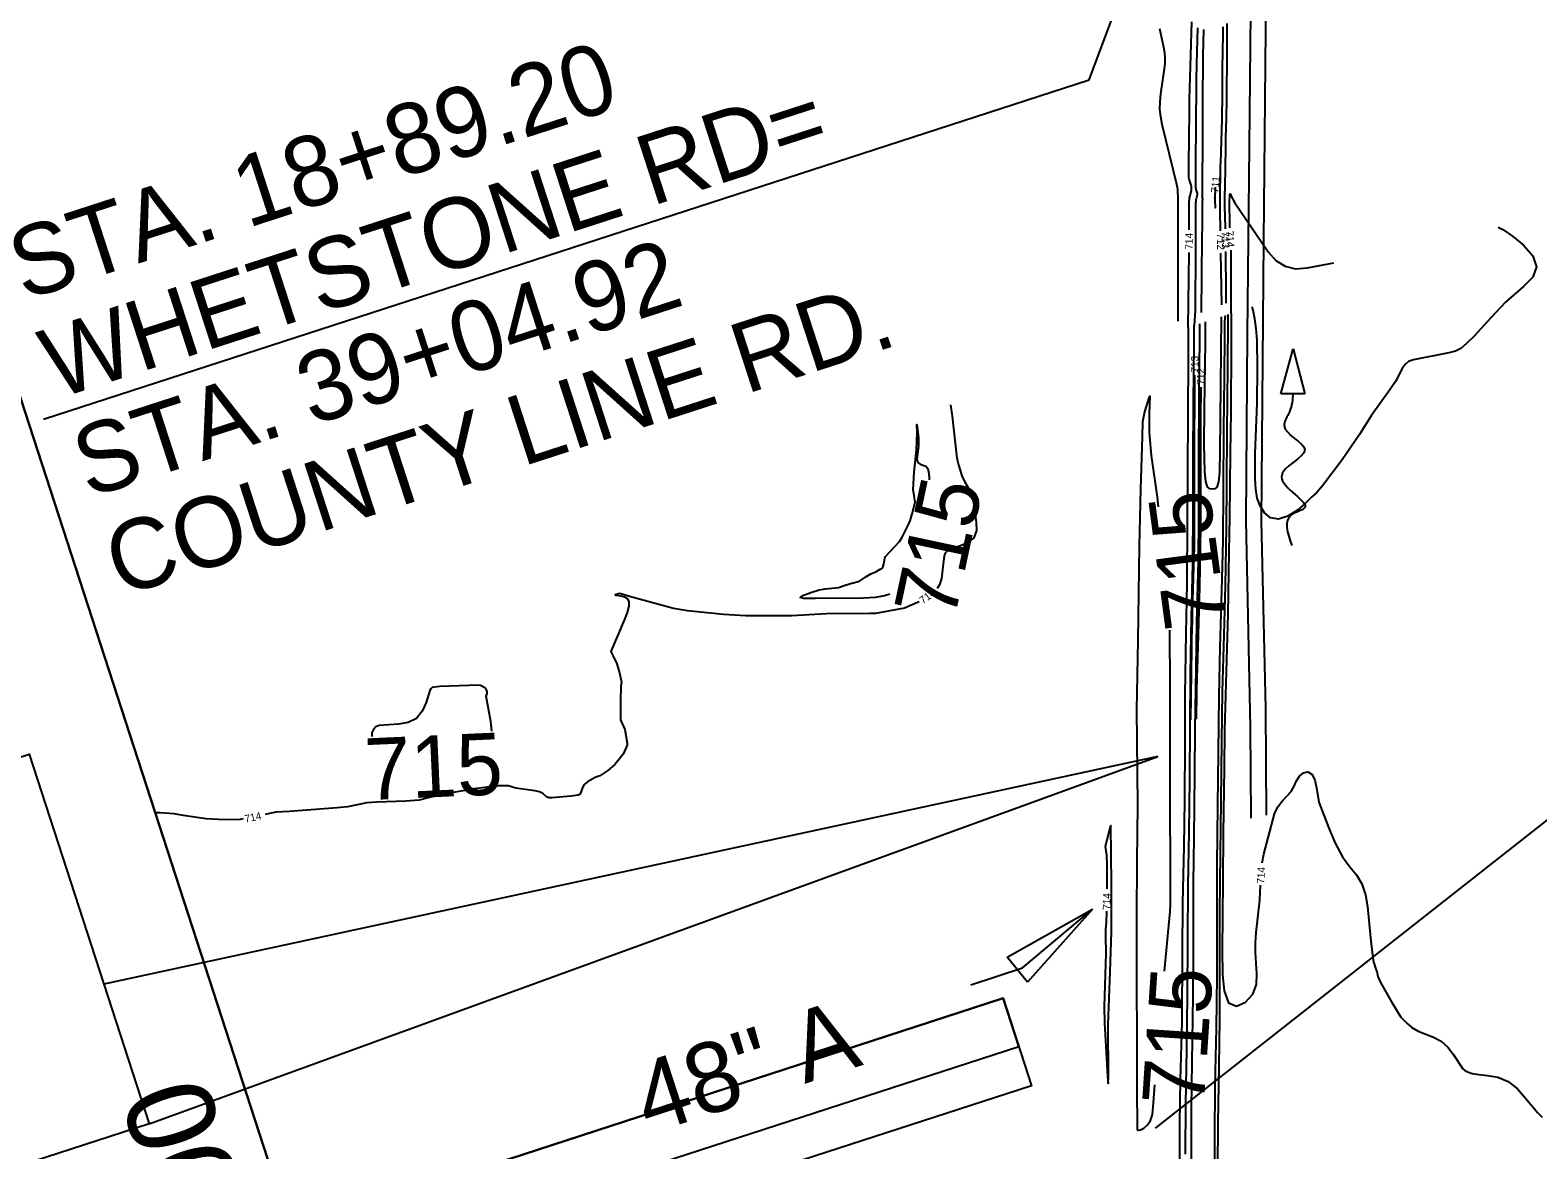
# Model space of a CAD drawing. Extents: x -468548933 to 3387700, y -306089263 to 1207014.
# Drawn here: x 1834585 to 1835390, y 535554 to 536152 of the extents above; entities that cross this region are included whole.
import ezdxf

# ---------------------------------------------------------------- set-up
doc = ezdxf.new("R2010")
doc.units = 0
for name, color, linetype in [('Default', 7, 'Continuous'), ('DT_X_Contour_Minor', 7, 'Continuous'), ('DT_X_Terrain_Ground_Line', 7, 'Continuous'), ('Level 19', 7, 'Continuous'), ('Level 40', 7, 'Continuous'), ('Level 56', 7, 'Continuous'), ('SC_Scratch1', 7, 'Continuous'), ('SC_Shading3', 7, 'Continuous')]:
    doc.layers.add(name, color=color, linetype=linetype)

msp = doc.modelspace()

# ---------------------------------------------------------------- linework, layer by layer
at = {"layer": 'Default'}
msp.add_lwpolyline([(1834724.08, 535511.25), (1834732.34, 535485.8), (1835112.79, 535609.32), (1835104.4, 535635.1)], close=True, dxfattribs=at)
at = {"layer": 'DT_X_Contour_Minor'}
for points in [[(1835197.92, 535996.77), (1835197.89, 536050.35), (1835197.89, 536051.63), (1835197.89, 536052.92), (1835197.88, 536054.21), (1835197.88, 536055.5), (1835197.85, 536061.41), (1835197.85, 536061.46), (1835197.85, 536061.5), (1835197.85, 536061.55), (1835197.84, 536061.59), (1835197.83, 536061.75), (1835197.83, 536061.78), (1835197.83, 536061.8), (1835197.83, 536061.83), (1835197.83, 536061.85), (1835197.85, 536061.94), (1835197.85, 536061.96), (1835197.85, 536061.97), (1835197.85, 536061.99), (1835197.85, 536062.01), (1835197.83, 536062.22), (1835197.83, 536062.26), (1835197.83, 536062.31), (1835197.82, 536062.35), (1835197.82, 536062.39), (1835197.7, 536066.32), (1835197.65, 536067.16), (1835197.56, 536067.99), (1835197.43, 536068.82), (1835197.25, 536069.64), (1835189.34, 536101.81), (1835188.55, 536105.85), (1835188.16, 536109.91), (1835188.19, 536113.98), (1835188.61, 536118.08), (1835190.66, 536131.48), (1835190.97, 536134.34), (1835191.01, 536137.2), (1835190.77, 536140.05), (1835190.27, 536142.89), (1835188.04, 536152.86)], [(1835203.7, 536045.43), (1835203.75, 536059.77), (1835203.78, 536060.75), (1835203.87, 536061.71), (1835204.01, 536062.67), (1835204.2, 536063.63), (1835204.92, 536066.74), (1835205.03, 536067.4), (1835205.05, 536068.06), (1835204.97, 536068.71), (1835204.81, 536069.37), (1835203.92, 536072.05), (1835203.76, 536072.63), (1835203.64, 536073.22), (1835203.57, 536073.82), (1835203.55, 536074.42), (1835203.57, 536077.84), (1835203.57, 536078.58), (1835203.58, 536079.31), (1835203.59, 536080.05), (1835203.59, 536080.78), (1835203.84, 536108.49), (1835203.84, 536109.14), (1835203.85, 536109.79), (1835203.85, 536110.45), (1835203.86, 536111.1), (1835203.87, 536113.23), (1835203.87, 536113.69), (1835203.88, 536114.15), (1835203.89, 536114.6), (1835203.9, 536115.06), (1835205.18, 536156.64)], [(1835208.27, 536153.42), (1835207.68, 536134.14), (1835207.6, 536131.29), (1835207.53, 536128.44), (1835207.49, 536125.59), (1835207.46, 536122.74), (1835207.4, 536113.43), (1835207.39, 536111.43), (1835207.37, 536109.44), (1835207.36, 536107.44), (1835207.34, 536105.45), (1835207.25, 536094.86), (1835207.23, 536092.59), (1835207.21, 536090.32), (1835207.2, 536088.05), (1835207.18, 536085.78), (1835207.09, 536068.9), (1835207.11, 536068.42), (1835207.16, 536067.95), (1835207.25, 536067.48), (1835207.39, 536067.01), (1835207.88, 536065.51), (1835207.96, 536065.19), (1835208, 536064.86), (1835207.99, 536064.53), (1835207.94, 536064.2), (1835207.43, 536062.02), (1835207.34, 536061.55), (1835207.27, 536061.07), (1835207.23, 536060.6), (1835207.21, 536060.12), (1835207.1, 536029.01), (1835207.07, 536022.34), (1835207.04, 536015.67), (1835206.99, 536009.01), (1835206.94, 536002.34), (1835206.35, 535994.34)], [(1835211.42, 536152.44), (1835211.21, 536145.65), (1835211.17, 536144.2), (1835211.14, 536142.74), (1835211.12, 536141.29), (1835211.11, 536139.83), (1835210.92, 536111.41), (1835210.91, 536110.25), (1835210.91, 536109.09), (1835210.9, 536107.92), (1835210.89, 536106.76), (1835210.85, 536102.95), (1835210.85, 536102.14), (1835210.84, 536101.32), (1835210.83, 536100.51), (1835210.83, 536099.69), (1835210.63, 536062.98), (1835210.63, 536062.82), (1835210.65, 536062.66), (1835210.68, 536062.51), (1835210.72, 536062.36), (1835210.88, 536061.87), (1835210.91, 536061.77), (1835210.92, 536061.66), (1835210.92, 536061.55), (1835210.9, 536061.45), (1835210.74, 536060.74), (1835210.71, 536060.58), (1835210.68, 536060.43), (1835210.67, 536060.27), (1835210.67, 536060.12), (1835210.63, 536050), (1835210.62, 536047.83), (1835210.61, 536045.67), (1835210.59, 536043.5), (1835210.58, 536041.33), (1835210.24, 536001.39)], [(1835220.52, 536045.04), (1835220.32, 536055.99), (1835220.28, 536058.52), (1835220.27, 536061.04), (1835220.27, 536063.56), (1835220.3, 536066.08), (1835220.43, 536074.32), (1835220.46, 536076.08), (1835220.5, 536077.85), (1835220.54, 536079.61), (1835220.59, 536081.37), (1835221.29, 536104.57), (1835221.36, 536107.24), (1835221.42, 536109.92), (1835221.46, 536112.59), (1835221.48, 536115.26), (1835221.53, 536123.99), (1835221.54, 536125.86), (1835221.56, 536127.74), (1835221.58, 536129.61), (1835221.6, 536131.48), (1835221.84, 536150), (1835221.91, 536153.97)], [(1835223.06, 536045.99), (1835222.93, 536053.4), (1835222.87, 536057.09), (1835222.85, 536060.78), (1835222.86, 536064.47), (1835222.91, 536068.17), (1835223.24, 536089.44), (1835223.28, 536091.74), (1835223.33, 536094.04), (1835223.38, 536096.34), (1835223.45, 536098.64), (1835223.67, 536106.15), (1835223.72, 536107.76), (1835223.75, 536109.37), (1835223.78, 536110.98), (1835223.79, 536112.59), (1835223.96, 536142.84), (1835223.97, 536144.61), (1835223.99, 536146.37), (1835224, 536148.14), (1835224.03, 536149.9), (1835224.1, 536155.67)], [(1835217.35, 536062.93), (1835217.37, 536061.9), (1835217.38, 536061.58), (1835217.4, 536061.25), (1835217.41, 536060.92), (1835217.44, 536060.59)], [(1835217.44, 536060.59), (1835217.64, 536057.97), (1835217.68, 536057.44), (1835217.71, 536057.26), (1835217.72, 536057.44), (1835217.72, 536057.97), (1835217.66, 536061.18), (1835217.66, 536061.24), (1835217.66, 536061.29), (1835217.66, 536061.34), (1835217.66, 536061.4), (1835217.66, 536061.58), (1835217.66, 536061.61), (1835217.66, 536061.65), (1835217.66, 536061.69), (1835217.67, 536061.73), (1835217.86, 536068.25)], [(1835225.41, 536046.63), (1835225.38, 536048.73), (1835225.36, 536060.1), (1835225.36, 536060.15), (1835225.36, 536060.2), (1835225.36, 536060.25), (1835225.36, 536060.3), (1835225.36, 536060.46), (1835225.36, 536060.49), (1835225.36, 536060.53), (1835225.36, 536060.56), (1835225.36, 536060.6), (1835225.41, 536063.93), (1835225.46, 536064.47), (1835225.58, 536064.67), (1835225.77, 536064.54), (1835226.04, 536064.06), (1835227.12, 536061.78), (1835227.36, 536061.29), (1835227.62, 536060.82), (1835227.89, 536060.35), (1835228.19, 536059.9), (1835245.93, 536033.8), (1835250.08, 536029.06), (1835254.95, 536026.05), (1835260.52, 536024.75), (1835266.81, 536025.18), (1835281.04, 536027.93)], [(1835368.77, 536046.89), (1835371.12, 536045.64), (1835376.4, 536042.17), (1835382.28, 536037.34), (1835387.21, 536031.65), (1835389.27, 536025.78), (1835387.24, 536020.32), (1835382.49, 536015.37), (1835372.62, 536006.96), (1835364.93, 535998.71), (1835355.88, 535988.79), (1835351.85, 535984.73), (1835348.76, 535982.19), (1835345.95, 535980.77), (1835342.45, 535979.82), (1835323.48, 535976.08), (1835320.86, 535975.13), (1835319, 535973.66), (1835317.52, 535971.37), (1835313.86, 535964.43), (1835310.93, 535960.04), (1835300.94, 535946.16), (1835294.71, 535936.14), (1835285.47, 535922.74), (1835274.98, 535908.7), (1835271.93, 535905.27), (1835268.98, 535902.76), (1835267.89, 535901.42), (1835265.55, 535899.11), (1835261.51, 535895.83), (1835256.49, 535892.65), (1835251.47, 535890.94), (1835247.25, 535891.67), (1835243.98, 535894.36), (1835241.63, 535898.12), (1835240.13, 535902.27), (1835239.32, 535906.94), (1835238.98, 535912.44), (1835239.06, 535925.82), (1835240.02, 535952.95), (1835240.24, 535971.66), (1835239.99, 535986.48), (1835239.54, 535992.75), (1835238.84, 535998.04), (1835237.9, 536002.52), (1835237.31, 536004.36)], [(1835203.26, 535993.34), (1835203.66, 536033.43)], [(1835221.24, 536005.51), (1835220.74, 536033.04)], [(1835223.47, 536006.35), (1835223.45, 536015.08), (1835223.43, 536020.35), (1835223.39, 536025.63), (1835223.33, 536030.9), (1835223.28, 536033.99)], [(1835226.25, 536000.78), (1835226.22, 536034.66)], [(1835220.89, 535999.05), (1835220.69, 535980.81), (1835220.46, 535962.08), (1835220.07, 535927.29), (1835219.87, 535916.08), (1835219.4, 535910.97), (1835218.56, 535908.12), (1835217.41, 535907.09), (1835216.09, 535906.95), (1835214.74, 535907.11), (1835213.53, 535908.18), (1835212.6, 535911.06), (1835212.07, 535916.22), (1835211.78, 535930.83), (1835212.02, 535950.35), (1835212.48, 535985.5), (1835212.49, 535996.33)], [(1835222.95, 535999.71), (1835222.67, 535996.49), (1835222.54, 535989.22), (1835222.38, 535966.9), (1835222.05, 535938.77), (1835221.85, 535907.06), (1835221.69, 535879.41), (1835221.05, 535852.75), (1835220.18, 535822.61), (1835219.65, 535796.36), (1835219.26, 535766.17), (1835218.93, 535738.1), (1835218.58, 535706.51), (1835218.49, 535678.66), (1835218.53, 535646.9), (1835218.16, 535619.26), (1835217.45, 535587.87), (1835217.29, 535561.21), (1835217.32, 535530.19)], [(1835224.48, 536000.21), (1835224.39, 535997.62), (1835224.24, 535971.9), (1835223.93, 535937.75), (1835223.68, 535910.05), (1835223.5, 535886.33), (1835222.91, 535855.51), (1835222.2, 535829.25), (1835221.37, 535798.83), (1835220.95, 535772.61), (1835220.57, 535740.12), (1835220.26, 535712.43), (1835220, 535681.09), (1835219.98, 535654.26), (1835219.95, 535624), (1835219.51, 535598.7), (1835219.01, 535568.51), (1835218.9, 535543.58)], [(1835226.25, 536000.78), (1835226.11, 535983.64), (1835225.91, 535948.36), (1835225.71, 535926.28), (1835225.36, 535892.3), (1835225, 535873.46), (1835224.33, 535840.28), (1835223.64, 535815.89), (1835222.62, 535778.11), (1835222.38, 535757.99), (1835221.98, 535723.13), (1835221.73, 535697.71), (1835221.42, 535660.69), (1835221.57, 535647.57), (1835222.46, 535638.98), (1835224.82, 535632.67), (1835229.01, 535630.9), (1835233.86, 535632.91), (1835237.78, 535637.21), (1835239.64, 535642.5), (1835239.91, 535648.21), (1835239.17, 535659.44), (1835239.13, 535664.77), (1835239.44, 535670.16), (1835241.44, 535687.51), (1835241.85, 535695.47)], [(1835203.26, 535993.34), (1835203.27, 535976.04), (1835203.07, 535948.1), (1835202.89, 535915.24), (1835202.76, 535889.76), (1835202.42, 535856.58), (1835201.98, 535829.94), (1835201.52, 535797.09), (1835201.41, 535771.81), (1835201.33, 535740.91), (1835200.86, 535716.11), (1835200.24, 535685.88), (1835200.09, 535659.63), (1835199.77, 535622.4), (1835199.01, 535591.48), (1835198.58, 535568.22), (1835198.63, 535537.99)], [(1835201.83, 535551.87), (1835201.89, 535578.71), (1835202.47, 535607.67), (1835202.92, 535636.46), (1835203.11, 535666.18), (1835203.25, 535695.25), (1835203.77, 535723.74), (1835204.11, 535751.9), (1835204.22, 535780.75), (1835204.52, 535808.35), (1835205, 535838.64), (1835205.62, 535866.89), (1835205.9, 535897), (1835205.89, 535923.11), (1835206.06, 535953.12), (1835206.34, 535985.59), (1835206.35, 535994.34)], [(1835205.08, 535542.71), (1835205.02, 535576.5), (1835205.35, 535600.74), (1835205.91, 535636.38), (1835206.08, 535661.62), (1835206.13, 535696.66), (1835206.44, 535720.9), (1835206.84, 535754.95), (1835207.02, 535778.9), (1835207.4, 535811.37), (1835207.84, 535835.77), (1835208.71, 535868.87), (1835208.96, 535892.79), (1835208.86, 535923.06), (1835209.08, 535955.93), (1835209.42, 535987.89), (1835209.38, 535995.32)], [(1835206.66, 535967.96), (1835206.65, 535967.25), (1835206.62, 535961.99), (1835206.59, 535956.73), (1835206.48, 535932.6), (1835206.46, 535927.43), (1835206.44, 535922.26), (1835206.43, 535917.09), (1835206.43, 535911.92), (1835206.42, 535886.88), (1835206.4, 535881.51), (1835206.34, 535876.15), (1835206.24, 535870.78), (1835206.11, 535865.42), (1835205.43, 535841.92), (1835205.29, 535836.88), (1835205.18, 535831.85), (1835205.08, 535826.81), (1835205.01, 535821.77), (1835204.53, 535783.83)], [(1835187.46, 535897.5), (1835186.76, 535902.71), (1835183.7, 535925.01), (1835182.63, 535937.25), (1835182.49, 535947.15), (1835182.85, 535956.74), (1835182.15, 535955.76), (1835179.88, 535948.36), (1835178.92, 535943), (1835178.61, 535935.01), (1835177.76, 535907.24), (1835177.07, 535876.47), (1835176.71, 535851.52), (1835176.31, 535826.43), (1835175.7, 535788.97), (1835175.82, 535772.65), (1835176.09, 535738.17), (1835175.85, 535708.05), (1835175.61, 535678.56), (1835175.72, 535641.08), (1835175.79, 535616.06), (1835175.78, 535588.21), (1835175.9, 535564.99), (1835176.12, 535564.67), (1835176.66, 535564.55), (1835177.74, 535564.85), (1835179.46, 535565.77), (1835181.43, 535567.4), (1835183.1, 535569.81), (1835184.1, 535572.95), (1835184.72, 535579.31), (1835185.34, 535588.75)], [(1835209.92, 535961.4), (1835209.89, 535954.12), (1835209.88, 535952.43), (1835209.87, 535950.73), (1835209.87, 535949.04), (1835209.87, 535947.34), (1835209.85, 535897.41), (1835209.81, 535886.71), (1835209.69, 535876.02), (1835209.5, 535865.32), (1835209.23, 535854.63), (1835207.94, 535810.24), (1835207.86, 535807.24), (1835207.79, 535804.24), (1835207.73, 535801.24), (1835207.69, 535798.23), (1835207.51, 535784.22)], [(1835076.3, 535952.05), (1835077.28, 535945.93), (1835079.73, 535923.55), (1835080.62, 535919.92), (1835082.39, 535914.08), (1835083.95, 535910.72), (1835088.13, 535903.94), (1835088.81, 535902.24), (1835089.19, 535900.5), (1835089.54, 535893.31), (1835090.1, 535889.29), (1835090.18, 535884.94), (1835088.78, 535881.06), (1835085.32, 535878.29), (1835080.86, 535876.42), (1835076.88, 535875.06), (1835074.51, 535873.88), (1835073.46, 535872.86), (1835072.95, 535871.36), (1835072.45, 535866.96), (1835071.57, 535859.23), (1835070.47, 535855.89), (1835069.22, 535854.01)], [(1835043.97, 535851), (1835041.16, 535850.11), (1835036.06, 535849.15), (1835029.94, 535848.69), (1835004.22, 535848.55), (1834997.86, 535848.67), (1834996.15, 535849.11), (1834996.89, 535849.95), (1835001.74, 535851.87), (1835006.21, 535853.22), (1835009.36, 535853.75), (1835016.62, 535854.54), (1835020.1, 535855.72), (1835023.64, 535856.76), (1835027.72, 535857.94), (1835031.18, 535860.15), (1835033.85, 535861.75), (1835036.51, 535862.76), (1835038.82, 535864.27), (1835039.83, 535864.79), (1835040.23, 535865.23), (1835040.81, 535867.09), (1835041.26, 535870.22), (1835041.7, 535870.98), (1835049.17, 535879.05), (1835050.6, 535881.37), (1835054.04, 535888.48), (1835054.84, 535890.14), (1835055.92, 535893.88), (1835057.39, 535900.01), (1835056.92, 535903.56), (1835056.35, 535906.61), (1835056.88, 535916.15), (1835058.15, 535927.86), (1835058.49, 535937.38), (1835058.34, 535941.58), (1835059.29, 535934.52), (1835059.19, 535930.23), (1835058.41, 535922.88), (1835058.84, 535921.25), (1835060.08, 535920.37), (1835063.23, 535919.21), (1835064.18, 535918.04), (1835064.83, 535915.37), (1835064.91, 535912.78), (1835064.88, 535911.94)], [(1835059.58, 535846.87), (1835058.73, 535846.4), (1835051.74, 535843.49), (1835036.37, 535840.63), (1835033.14, 535840.5), (1835010.14, 535840.45), (1834991.55, 535839.43), (1834966.94, 535839.38), (1834955.14, 535840.02), (1834935.91, 535841.95), (1834928.51, 535843.23), (1834905.01, 535849.65), (1834899.75, 535851.2), (1834897.76, 535850.81), (1834897.34, 535850.56), (1834897.77, 535850.41), (1834900.5, 535850.01), (1834902.24, 535849.52), (1834903.76, 535848.57), (1834904.67, 535846.95), (1834904.66, 535844.47), (1834903.79, 535841.14), (1834902.18, 535836.98), (1834895.03, 535820.34), (1834896.06, 535818.22), (1834898.19, 535813.63), (1834899.57, 535808.91), (1834900.61, 535804), (1834900.37, 535801.91), (1834900.18, 535793.63), (1834900.14, 535783.86), (1834902.47, 535778.68), (1834903.78, 535771.41), (1834903.67, 535770.23), (1834901.58, 535765.37), (1834899.69, 535762.95), (1834897.14, 535759.99), (1834893.33, 535756.79), (1834889.17, 535753.96), (1834886.71, 535752.95), (1834882.46, 535750.65), (1834880.64, 535749.02), (1834879.68, 535747.2), (1834878.64, 535744.15), (1834877.52, 535743.47), (1834873.59, 535743.07), (1834863.51, 535742.06), (1834861.82, 535742.17), (1834860.56, 535742.62), (1834858.62, 535744.39), (1834856.98, 535745.27), (1834854.41, 535745.87), (1834844.22, 535747.26), (1834840.21, 535748.56), (1834834.85, 535748.56), (1834822.04, 535746.91), (1834803.68, 535743.76), (1834792.66, 535740.92), (1834785.49, 535740.31), (1834770.04, 535739.89), (1834764.74, 535739.46), (1834754.42, 535737.33), (1834748.88, 535736.77), (1834723.38, 535734.85), (1834716.09, 535734.4), (1834711.19, 535733.34), (1834710.5, 535733.19)], [(1835190.5, 535649.49), (1835193.61, 535681.39), (1835193.83, 535685), (1835193.71, 535703.61), (1835193.61, 535739.9), (1835193.68, 535769.88), (1835193.53, 535801.1), (1835193.46, 535831.64)], [(1834831.46, 535777.8), (1834830.91, 535782.82), (1834828.5, 535796.49), (1834828.89, 535797.83), (1834828.96, 535798.81), (1834828.65, 535799.87), (1834827.8, 535800.84), (1834825.42, 535802.14), (1834824.29, 535802.33), (1834803.69, 535801.54), (1834799.61, 535801.07), (1834798.84, 535800.43), (1834798.34, 535799.4), (1834796.34, 535793.08), (1834794.33, 535788.47), (1834791.17, 535784.56), (1834786.71, 535782.34), (1834781.68, 535781.46), (1834771.25, 535780.78), (1834769.53, 535780.02), (1834768.24, 535778.68), (1834767.46, 535776.85), (1834767.41, 535774.82)], [(1835242.67, 535707.44), (1835243.53, 535712.01), (1835249.38, 535733.5), (1835251.13, 535737.35), (1835253.48, 535740.38), (1835258.26, 535745.51), (1835259.81, 535748.37), (1835261.06, 535751.27), (1835262.58, 535753.78), (1835264.74, 535755.48), (1835267.18, 535755.93), (1835269.34, 535754.67), (1835270.82, 535751.55), (1835271.69, 535747.55), (1835273.03, 535739.74), (1835278.32, 535725.89), (1835281.72, 535717.91), (1835285.55, 535710.57), (1835289.45, 535705.2), (1835293.02, 535700.92), (1835295.9, 535696.28), (1835297.81, 535690.34), (1835298.91, 535684.1), (1835300.75, 535665.66), (1835302.06, 535655.28), (1835302.81, 535652.28), (1835304.06, 535648.65), (1835304.5, 535646.77), (1835305.87, 535643.5), (1835311.79, 535633.12), (1835316.79, 535625), (1835319.97, 535621.73), (1835322.61, 535619.5), (1835326, 535617.44), (1835334.25, 535614.38), (1835338.32, 535612.21), (1835341.85, 535608.97), (1835344.67, 535605.3), (1835349.79, 535597.35), (1835350.81, 535596.59), (1835352.39, 535595.74), (1835354.79, 535594.92), (1835358.31, 535594.28), (1835363.06, 535593.81), (1835368.52, 535592.87), (1835374.03, 535590.65), (1835378.99, 535586.68), (1835383.29, 535581.8), (1835389.83, 535573.86), (1835392.25, 535571.62)], [(1834698.73, 535730.86), (1834697.13, 535730.63), (1834688.87, 535730.35), (1834678.96, 535730.95), (1834667.89, 535732.59), (1834661.65, 535733.5), (1834654.53, 535734.06), (1834651.75, 535734.04)], [(1835159.61, 535681.51), (1835159.47, 535675.32), (1835159.1, 535671.91), (1835159.15, 535668.23), (1835159.23, 535659.11), (1835158.39, 535630.76), (1835158.46, 535621.74), (1835158.88, 535615.72), (1835160.1, 535593.22), (1835160.47, 535589.5), (1835160.6, 535593.41), (1835160.45, 535620.87), (1835161.57, 535649.29), (1835162.29, 535670.33), (1835162.21, 535696.19), (1835161.98, 535727.38), (1835161.5, 535726.71), (1835158.99, 535716.19), (1835159.56, 535711.56), (1835159.86, 535706.19), (1835159.8, 535693.51)]]:
    msp.add_lwpolyline(points, dxfattribs=at)
at = {"layer": 'DT_X_Terrain_Ground_Line'}
msp.add_line((1835055.83, 534489.39), (1834448.38, 536360.46), dxfattribs=at)
at = {"layer": 'Level 40'}
for p, q in [((1835150.33, 536125.71), (1835207.87, 536279.41)), ((1834592.06, 535944.47), (1835150.33, 536125.71)), ((1835185.71, 535565.7), (1835593.63, 535886.58)), ((1835106.63, 535657.04), (1835152.18, 535682.72)), ((1835114.69, 535651.24), (1835152.18, 535682.72)), ((1835152.18, 535682.72), (1835117.42, 535643.67)), ((1835087.12, 535642.3), (1835114.69, 535651.24)), ((1835117.42, 535643.67), (1835106.63, 535657.04))]:
    msp.add_line(p, q, dxfattribs=at)
for points in [[(1834648.53, 535567.95), (1834128.38, 535399.08), (1834064.25, 535596.62), (1834584.4, 535765.49)], [(1835187.07, 535764.16), (1834624.31, 535642.57), (1834648.53, 535567.95)]]:
    msp.add_lwpolyline(points, close=True, dxfattribs=at)
at = {"layer": 'Level 56'}
for p, q in [((1835252.68, 535958), (1835259.31, 535981.95)), ((1835259.31, 535981.95), (1835265.56, 535957.91)), ((1835265.56, 535957.91), (1835252.68, 535958))]:
    msp.add_line(p, q, dxfattribs=at)
for points in [[(1835236.83, 535731.29), (1835236.49, 535779.79), (1835234.2, 535890.01), (1835234.88, 535990.01), (1835236.04, 536090), (1835236.78, 536179.8), (1835240.03, 536230.98)], [(1835248.03, 536230.78), (1835244.89, 536189.94), (1835243.5, 536039.95), (1835242.2, 535889.95), (1835244.43, 535789.94), (1835244.77, 535732.8)]]:
    msp.add_lwpolyline(points, dxfattribs=at)
msp.add_spline([(1835259.06, 535957.98), (1835259.05, 535957.03), (1835256.73, 535947.17), (1835254.51, 535940.94), (1835265.45, 535928.13), (1835252.97, 535913.67), (1835265.22, 535896.78), (1835258.5, 535893.43), (1835258.56, 535876.96)], degree=3, dxfattribs=at)
at = {"layer": 'SC_Scratch1'}
msp.add_lwpolyline([(1834448.38, 536360.46), (1835055.83, 534489.39), (1836664.2, 534206.16), (1839225.76, 534394.17), (1842361.7, 536308.3), (1842189.37, 536805.14), (1841581.79, 538676.58), (1840313.7, 539042.49), (1837357.67, 538260.17), (1834781.04, 538194.31), (1834403.13, 536496.43)], close=True, dxfattribs=at)
at = {"layer": 'SC_Shading3'}
msp.add_lwpolyline([(1834739.13, 535464.87), (1834724.08, 535511.25), (1835104.4, 535635.1), (1835119.61, 535588.39)], close=True, dxfattribs=at)

# ---------------------------------------------------------------- texts
at = {"layer": 'DT_X_Terrain_Ground_Line'}
msp.add_text('MATCH LINE                 STA. 1690+00', height=46.8, rotation=107.98637, dxfattribs=at).set_placement((1835009.73, 534572.14))
at = {"layer": 'Level 19'}
for s, height, rotation, p in [('711', 4, 84.5446, (1835219.33, 536065.09)), ('714', 4, 89.79861, (1835205.67, 536034.95)), ('712', 4, 271.0498, (1835218.54, 536043.65)), ('713', 4, 271.02826, (1835221.09, 536044.63)), ('714', 4, 273.85457, (1835223.4, 536044.97)), ('713', 4, 89.55652, (1835208.66, 535969.27)), ('712', 4, 89.61415, (1835211.92, 535962.74)), ('715', 33, 77.94518, (1835078.28, 535836.55)), ('715', 33, 97.58617, (1835224.04, 535834.63)), ('714', 4, 35.76976, (1835061.56, 535845.47)), ('715', 33, 2.58977, (1834764.32, 535740.83)), ('714', 4, 12.36443, (1834699.98, 535728.83)), ('714', 4, 87.11823, (1835243.88, 535696.16)), ('714', 4, 88.69387, (1835161.63, 535682.25)), ('715', 33, 86.23588, (1835211.52, 535577.01))]:
    msp.add_text(s, height=height, rotation=rotation, dxfattribs=at).set_placement(p)
at = {"layer": 'Level 40'}
for s, p in [('STA. 18+89.20', (1834581.63, 536007.62)), ('WHETSTONE RD=', (1834598.77, 535954.83)), ('STA. 39+04.92', (1834615.91, 535902.05)), ('COUNTY LINE RD.', (1834633.05, 535849.26)), ('48" A', (1834915.21, 535562.3))]:
    msp.add_text(s, height=37.5, rotation=17.9864, dxfattribs=at).set_placement(p)

doc.saveas('drawing.dxf')
